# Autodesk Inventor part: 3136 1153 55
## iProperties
Shininess: 60.0
Length Units: 11269
Angle Units: 11279
Time Units: 11290
Mass Units: 11283
Length Display Precision: 3
Angle Display Precision: 2
Compacted: True
Created: 2000-11
Part Number: 3136 1153 55
Material: Steel, Mild
Description: Pipe
Document SubType Name: Sheet Metal
Designer: Joe M
Engineer: Joe M
Density: 0.0
Volumn: 0.0
Area: 0.0
PropertySet Name: Model Information
Control State: 0
Master: False
Checked Out: False
Last Check In By: brjdn
Last Check In Date: 2001-04-05
Title: Fäste för skyddsbåge
Author: Joe M
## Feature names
1. Extrusion4
2. Extrusion5
3. Fillet1
4. FlatPatternExtrusion1
